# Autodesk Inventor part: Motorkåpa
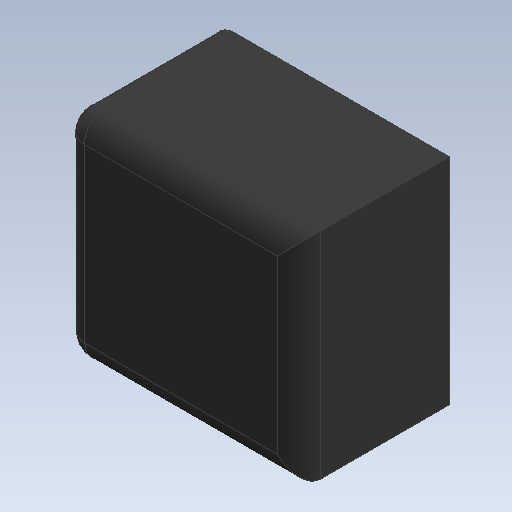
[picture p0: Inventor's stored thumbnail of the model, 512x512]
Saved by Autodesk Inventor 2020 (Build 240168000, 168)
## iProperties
Created: 2019-07
Part Number: Motorkåpa
Material: Rubber
Document SubType Name: Modeling
Designer: cl
Density: 0.93 g/cm^3
Appearance: Rubber - Black
Author: cl
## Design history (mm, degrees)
sketch "Sketch1"
  geometry: L1 (-195.591, 30)-(-195.591, 50) reference; L2 (-195.591, 50)-(-295.546, 50) reference; L3 (-305.546, 39.955)-(-305.185, -40.045) reference; L4 (-295.185, -50)-(-195.591, -50) reference; L5 (-195.591, -50)-(-195.591, -30) reference; L6 (-195.591, -30)-(-195.591, 30) reference; A1 r 10 centre (-295.185, -40) between (-305.185, -40.045) and (-295.185, -50) reference; A2 r 10 centre (-295.546, 40) between (-295.546, 50) and (-305.546, 39.955) reference; 1 further point
extrude "Extrusion1" new body sketch "Sketch1" distance "d0" = 70; taper "d1" = 0 deg
fillet "Fillet1" dims "d2" = 10
body "Solid1"
node "Reference1"
